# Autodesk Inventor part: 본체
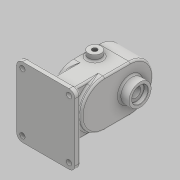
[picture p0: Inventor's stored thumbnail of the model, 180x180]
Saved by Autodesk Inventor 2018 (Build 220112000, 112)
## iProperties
Created: 2020-09
Part Number: 본체
Material: 일반
Document SubType Name: Modeling
Designer: home
Density: 1 g/cm^3
Appearance: 기본값
Author: home
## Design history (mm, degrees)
sketch "스케치1"
  geometry: L1 (-40, 60)-(40, 60); L2 (50, 50)-(50, -50); L3 (40, -60)-(-40, -60); L4 (-50, -50)-(-50, 50); C1 r 4.5 at (-40, 50); C2 r 4.5 at (-40, -50); C3 r 4.5 at (40, -50); C4 r 4.5 at (40, 50); A1 r 10 centre (-40, 50) between (-40, 60) and (-50, 50); A2 r 10 centre (-40, -50) between (-50, -50) and (-40, -60); A3 r 10 centre (40, -50) between (40, -60) and (50, -50); A4 r 10 centre (40, 50) between (50, 50) and (40, 60); 6 further points
  constraints: 8 centre point, 8 end point, 8 point on circle, 8 tangent, 6 point on line, 4 coincident, 3 equal radius, 2 midpoint, 2 parallel, 1 horizontal, 1 horizontal alignment, 1 perpendicular, 1 vertical alignment
  dimensions: "d0" = 120 distance of point (-50, -60) point (-50, 60); "d1" = 100 distance of point (-50, 60) point (50, 60); "d2" = 10 radius of A1; "d3" = 9 diameter of C1; "d4" = 9 diameter of C2; "d5" = 9 diameter of C3; "d6" = 9 diameter of C4
extrude "돌출1" new body sketch "스케치1" stored distance "d7" = 10; taper "d8" = 0 deg
node "작업 평면1"
sketch "스케치2"
  geometry: L1 (-100, 0)-(0, 0) reference; L2 (-50, 0)-(-50, 90); L3 (-50, 90)-(-50, 112); L4 (-50, 90)-(-50, 68); L5 (-90, 112)-(-90, 68); L6 (-10, 112)-(-10, 68); A1 r 40 centre (-50, 68) between (-90, 68) and (-10, 68); A2 r 40 centre (-50, 112) between (-10, 112) and (-90, 112); 1 further point
  constraints: 10 end point, 4 point on circle, 4 vertical, 3 tangent, 2 centre point, 2 coincident, 1 midpoint, 1 point on line
  dimensions: "d10" = 90 distance of L2.start L2.end; "d11" = 22 distance of L2.end L3.end; "d12" = 22 distance of L2.end L4.end; "d19" = 40 radius of A2
extrude "돌출2" join sketch "스케치2" distance "d15" = 53; taper "d16" = 0 deg
sketch "스케치3"
  geometry: L1 (10, 112)-(10, 68) reference; L2 (90, 68)-(90, 112) reference; L3 (26, 112)-(26, 68); L4 (74, 112)-(74, 68); A1 r 40 centre (50, 68) between (10, 68) and (90, 68) reference; A2 r 40 centre (50, 112) between (90, 112) and (10, 112) reference; A3 r 24 centre (50, 112) between (74, 112) and (26, 112); A4 r 24 centre (50, 68) between (26, 68) and (74, 68); 1 further point
  constraints: 4 end point, 4 point on circle, 2 centre point, 2 coincident, 2 tangent, 2 vertical
  dimensions: "d20" = 24 radius of A3; "d21" = 24 radius of A4
extrude "돌출3" cut sketch "스케치3" distance "d22" = 29; taper "d23" = 0 deg
sketch "스케치5"
  geometry: L1 (-10, 112)-(-10, 68) reference; L2 (-90, 68)-(-90, 112) reference; C1 r 19 at (-50, 112); A1 r 40 centre (-50, 112) between (-10, 112) and (-90, 112) reference; A2 r 40 centre (-50, 68) between (-90, 68) and (-10, 68) reference; 1 further point
  constraints: 1 centre point, 1 coincident
  dimensions: "d29" = 38 diameter of C1
extrude "돌출4" join sketch "스케치5" distance "d30" = 17; taper "d31" = 0 deg
sketch "스케치6"
  geometry: L1 (33, 107)-(-20, 107) reference; L2 (9, 107)-(50, 107); L3 (9, 63)-(9, 107) reference; L4 (9, 107)-(9, 119.5); L5 (9, 107)-(9, 131) reference; L6 (9, 119.5)-(24, 119.5); L7 (50, 88)-(50, 126) reference; L8 (50, 107)-(50, 121.404); L9 (49.3, 121)-(43.2, 121); L10 (42.7, 120.5)-(42.7, 115.5); L11 (24, 119.5)-(24, 115.5); L12 (24, 115.5)-(42.7, 115.5); L13 (49.3, 121)-(50, 121.404); A1 r 0.5 centre (43.2, 120.5) between (43.2, 121) and (42.7, 120.5); 3 further points
  constraints: 18 end point, 7 point on line, 3 perpendicular, 2 point on circle, 2 tangent, 2 vertical, 1 centre point, 1 collinear, 1 midpoint
  dimensions: "d32" = 12.5 distance of L3.end L4.end; "d33" = 15 distance of L4.end L6.end; "d34" = 14 distance of L2.end point (50, 121); "d35" = 7.3 distance of point (50, 121) point (42.7, 121); "d36" = 4 distance of L6.end L11.end; "d37" = 0.5 radius of A1; "d38" = 0.7 distance of L9.start point (50, 121); "d39" = 150 deg angle of L9 L13
revolve "회전1" sketch "스케치6" stored, may be unused: angle "d41" = 90 deg
sketch "스케치7"
  geometry: L1 (26, 68)-(26, 112) reference; L2 (74, 112)-(74, 68) reference; C1 r 12.5 at (50, 112) reference; C2 r 12.5 at (50, 68); A1 r 24 centre (50, 68) between (26, 68) and (74, 68) reference; A2 r 24 centre (50, 112) between (74, 112) and (26, 112) reference; 1 further point
  constraints: 1 centre point, 1 coincident
  dimensions: "d42" = 25 diameter of C2
extrude "돌출5" cut sketch "스케치7" distance "d43" = 15; taper "d44" = 0 deg
sketch "스케치8"
  geometry: L1 (0, 0)-(0, 44) reference; L2 (0, 44)-(-53, 44) reference; L3 (-53, 0)-(-53, 44) reference; L4 (0, 0)-(-53, 0) reference; L5 (-53, 22)-(-39, 22); C1 r 11 at (-39, 22); 1 further point
  constraints: 2 end point, 1 centre point, 1 coincident, 1 horizontal, 1 midpoint
  dimensions: "d45" = 14 distance of L5.start L5.end; "d46" = 22 diameter of C1
extrude "돌출6" join sketch "스케치8" distance "d47" = 10; taper "d48" = 0 deg
sketch "스케치10"
  geometry: C1 r 11 at (0, 0) reference; 2 further points
  constraints: 1 coincident
hole "구멍2" sketch "스케치10" at (0, 0) diameter "d56" = 8.376; stored, may be unused: countersink angle "d60" = 90 deg, drill point angle "d62" = 118 deg; dims "d57" = 29, "d58" = 4, "d59" = 2, "d61" = 30
sketch "스케치11"
  geometry: L1 (26, 68)-(26, 112) reference; L2 (74, 112)-(74, 68) reference; L3 (10, 112)-(10, 68) reference; L4 (90, 68)-(90, 112) reference; L5 (19, 112)-(19, 68); L6 (81, 112)-(81, 68); L7 (50, 112)-(19, 112); L8 (50, 68)-(19, 68); L9 (50, 68)-(81, 68); L10 (50, 112)-(81, 112); L11 (50, 143)-(50, 37); C1 r 8.5 at (50, 112) reference; A1 r 24 centre (50, 68) between (26, 68) and (74, 68) reference; A2 r 24 centre (50, 112) between (74, 112) and (26, 112) reference; A3 r 40 centre (50, 68) between (10, 68) and (90, 68) reference; A4 r 40 centre (50, 112) between (90, 112) and (10, 112) reference; A5 r 31 centre (50, 112) between (19, 112) and (81, 112); A6 r 31 centre (50, 68) between (19, 68) and (81, 68); 3 further points
  constraints: 14 end point, 6 coincident, 6 point on circle, 2 centre point, 2 horizontal, 2 vertical, 1 parallel
  dimensions: "d63" = 62 diameter of A5; "d64" = 62 diameter of A6; "d65" = 24 distance between parallel lines of L2 L11
hole "구멍3" sketch "스케치11" at (19, 112), (19, 68), (50, 143), (50, 37), (81, 112), (81, 68) diameter "d66" = 4.134; stored, may be unused: countersink angle "d70" = 90 deg, drill point angle "d72" = 118 deg; dims "d67" = 10, "d68" = 4, "d69" = 2, "d71" = 12
chamfer "모따기1" distance "d73" = 1; stored, may be unused: second distance "d74" = 2, angle "d75" = 45 deg
sketch "스케치12"
  geometry: L1 (50, 50)-(50, -50) reference; L2 (50, 0)-(25, 0); L3 (25, 0)-(25, -40); L4 (25, -40)-(-12, -40); L5 (-12, -40)-(-12, 40); L6 (-12, 40)-(25, 40); L7 (25, 40)-(25, 0); 1 further point
  constraints: 12 end point, 5 perpendicular, 1 horizontal, 1 midpoint, 1 point on line
  dimensions: "d76" = 25 distance of L2.start L2.end; "d77" = 40 distance of L2.end L3.end; "d78" = 37 distance of L3.end L4.end; "d79" = 80 distance of L4.end L5.end
extrude "돌출7" join sketch "스케치12" stored distance "d80" = 10; taper "d81" = 0 deg
fillet "모깎기1" dims "d82" = 3
fillet "모깎기2" dims "d83" = 3
fillet "모깎기3" dims "d84" = 3
fillet "모깎기4" dims "d85" = 3
fillet "모깎기5" dims "d86" = 3
sketch "스케치13"
  geometry: L1 (-50, 50)-(-50, -50) reference; 2 further points
  constraints: 1 other
  dimensions: "d87" = 0 vertical distance of point (0, 0) point (-38, 0)
feature "엠보싱1" sketch "스케치13" dims "d0" = 120, "d89" = 0.5, "d90" = 0
node "솔리드1"
mirror "미러1"
mirror "미러2"
node "투영된 루프1"
node "투영된 루프3"
node "투영된 루프4"
node "투영된 루프5"
node "투영된 루프7"
node "투영된 루프8"
other parameters: "d9" = -17, "d17" = 48, "d18" = 48
